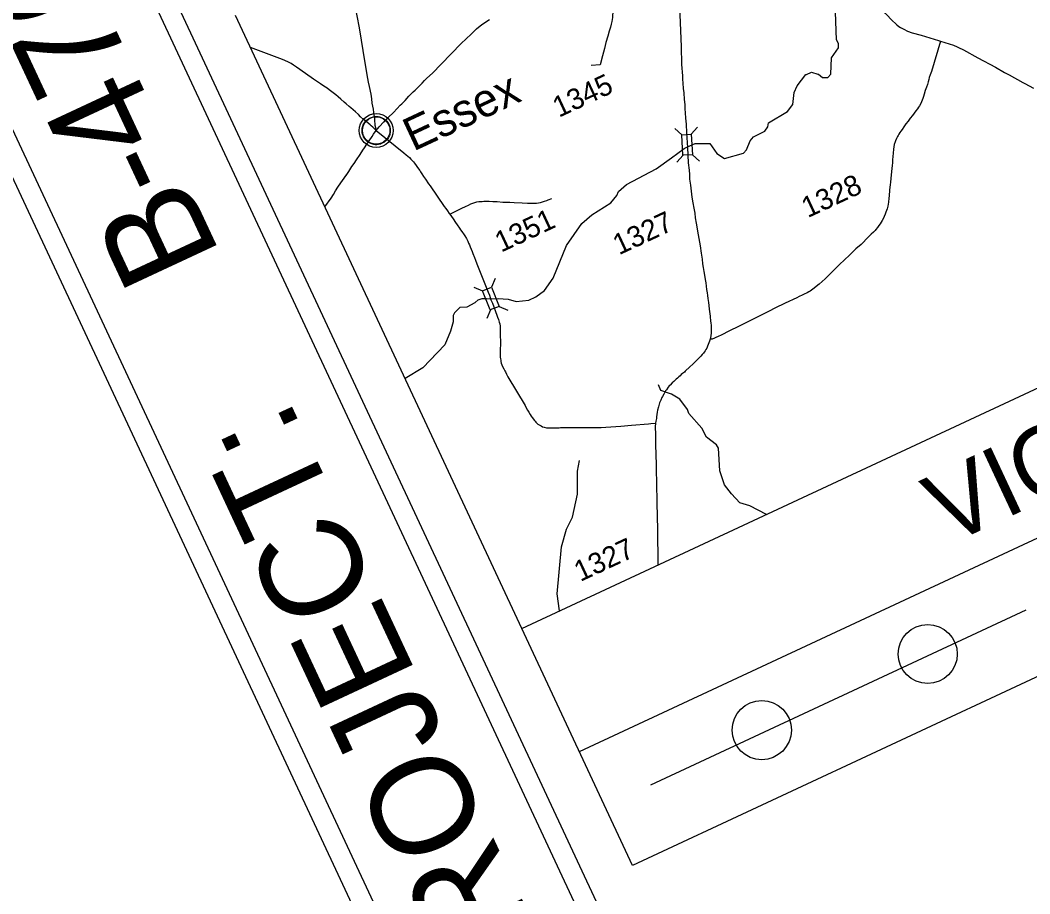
# Model space of a CAD drawing. Extents: x 2318983 to 2324558, y 920396 to 924651.
# Drawn here: x 2320105 to 2320702, y 922262 to 922780 of the extents above; entities that cross this region are included whole.
import ezdxf

# ---------------------------------------------------------------- set-up
doc = ezdxf.new("R2010")
doc.units = 0
for name, color, linetype in [('Exist Civil Demographics City Label', 7, 'Continuous'), ('Exist Civil Demographics Community CELL', 7, 'Continuous'), ('Exist Hydrographic Creek Single Shore', 7, 'Continuous'), ('Exist Road Primary NC Attributed', 7, 'Continuous'), ('Exist Road Secondary Structure Standard Bridge CELL', 7, 'Continuous'), ('Exist Road Secondary Type 51 Attributed', 7, 'Continuous'), ('Exist Road Secondary Type 51 Number Label', 7, 'Continuous'), ('Pattern 3', 7, 'Continuous'), ('Sheet Title CELL', 7, 'Continuous')]:
    doc.layers.add(name, color=color, linetype=linetype)

msp = doc.modelspace()

# ---------------------------------------------------------------- linework, layer by layer
at = {"layer": 'Exist Civil Demographics Community CELL'}
msp.add_lwpolyline([(2320307.18, 922715.51), (2320307.28, 922716.1), (2320307.47, 922716.8), (2320307.78, 922717.57), (2320308.09, 922718.18), (2320308.45, 922718.79), (2320308.85, 922719.33), (2320309.27, 922719.8), (2320309.75, 922720.29), (2320310.34, 922720.77), (2320310.92, 922721.16), (2320311.44, 922721.47), (2320311.98, 922721.73), (2320312.56, 922721.97), (2320313.15, 922722.17), (2320313.61, 922722.29), (2320314.13, 922722.37), (2320314.57, 922722.44), (2320315.25, 922722.47), (2320315.72, 922722.46), (2320316.32, 922722.43), (2320316.84, 922722.35), (2320317.36, 922722.25), (2320317.89, 922722.1), (2320318.44, 922721.89), (2320319.15, 922721.58), (2320319.82, 922721.21), (2320320.35, 922720.84), (2320320.9, 922720.41), (2320321.25, 922720.08), (2320321.69, 922719.61), (2320322.1, 922719.11), (2320322.43, 922718.62), (2320322.76, 922718.09), (2320323.02, 922717.54), (2320323.24, 922717.01), (2320323.41, 922716.48), (2320323.54, 922715.99), (2320323.66, 922715.34), (2320323.72, 922714.85), (2320323.75, 922714.21), (2320323.73, 922713.59), (2320323.67, 922712.99), (2320323.57, 922712.41), (2320323.4, 922711.75), (2320323.2, 922711.13), (2320322.95, 922710.59), (2320322.62, 922709.95), (2320322.27, 922709.39), (2320321.9, 922708.89), (2320321.45, 922708.38), (2320320.89, 922707.86), (2320320.36, 922707.42), (2320319.83, 922707.05), (2320319.37, 922706.79), (2320318.64, 922706.44), (2320317.88, 922706.15), (2320317.25, 922706), (2320316.55, 922705.86), (2320316.08, 922705.81), (2320315.6, 922705.78), (2320315.01, 922705.78), (2320314.55, 922705.83), (2320313.95, 922705.91), (2320313.32, 922706.04), (2320312.84, 922706.18), (2320312.29, 922706.38), (2320311.8, 922706.59), (2320311.38, 922706.83), (2320310.66, 922707.26), (2320310.07, 922707.72), (2320309.54, 922708.2), (2320309.07, 922708.71), (2320308.73, 922709.13), (2320308.42, 922709.58), (2320307.98, 922710.33), (2320307.8, 922710.71), (2320307.61, 922711.14), (2320307.34, 922712.01), (2320307.18, 922712.75), (2320307.1, 922713.3), (2320307.07, 922713.97), (2320307.06, 922714.47), (2320307.12, 922715.16)], close=True, dxfattribs=at)
for centre, radius in [((2320315.43, 922714.19), 10.03), ((2320315.4, 922714.22), 8.15)]:
    msp.add_circle(centre, radius, dxfattribs=at)
at = {"layer": 'Exist Hydrographic Creek Single Shore'}
for points in [[(2320569.9, 922747.45), (2320570.2, 922747.45), (2320573.22, 922748.68), (2320576.86, 922747.53), (2320577.28, 922747.53), (2320579.77, 922745.64), (2320582.84, 922745.68), (2320584.66, 922747.61), (2320585.03, 922757.16), (2320589.07, 922763.14), (2320589.24, 922765.65), (2320587.98, 922767.86), (2320587.39, 922784.23)], [(2320458.96, 922678.09), (2320463.64, 922682.08), (2320481.15, 922691.44), (2320490.31, 922697.95), (2320497.86, 922703.42), (2320499.84, 922704.47), (2320504.27, 922706.5), (2320513.06, 922706.43), (2320517.02, 922700.5), (2320521.68, 922697.62), (2320532.9, 922700.83), (2320534.72, 922702.68), (2320536.93, 922708.02), (2320538.75, 922710.36), (2320545.47, 922713.86), (2320547.29, 922716.36), (2320547.68, 922718.64), (2320558.88, 922725.48), (2320562.1, 922729.65), (2320562.86, 922736.79), (2320564.66, 922740.74), (2320569.9, 922747.45)], [(2320365.22, 922609.48), (2320369.31, 922609.73), (2320374, 922612.18), (2320375.85, 922613.75), (2320378.12, 922614.68), (2320380.69, 922614.52), (2320383.29, 922614.46), (2320387.65, 922614.62), (2320393.49, 922614.14), (2320398.38, 922612.86), (2320405.74, 922613.56), (2320410.02, 922615.52), (2320415.11, 922619.44), (2320420.16, 922626.67), (2320428.16, 922645.98), (2320437.24, 922659.03), (2320443.11, 922664.2), (2320454.31, 922671.28), (2320457.95, 922675.63), (2320458.96, 922678.09)], [(2320365.22, 922609.48), (2320361.77, 922606.11), (2320360.96, 922604.46), (2320361.01, 922600.83), (2320359.41, 922595.27), (2320356.02, 922587.22), (2320343.05, 922573.52), (2320332.54, 922567.22)], [(2320365.22, 922609.48), (2320361.77, 922606.11), (2320360.96, 922604.46), (2320361.01, 922600.83), (2320359.41, 922595.27), (2320356.02, 922587.22), (2320347.23, 922577.93)], [(2320546.51, 922486.67), (2320536.59, 922491.83), (2320530.83, 922493.61), (2320525.86, 922498.9), (2320521.7, 922504.14), (2320518.95, 922512.5), (2320518.18, 922525.88), (2320516.95, 922527.85), (2320510.95, 922532.36), (2320508.22, 922537.82), (2320500.54, 922546.55), (2320499.7, 922548.78), (2320495.13, 922554.89), (2320490.18, 922557.92), (2320484.01, 922560.09), (2320482.53, 922563.42)], [(2320423.87, 922429.44), (2320422.57, 922439.58), (2320425.15, 922467.47), (2320428.11, 922477.93), (2320431.72, 922484.94), (2320434.65, 922498.71), (2320434.7, 922512.27), (2320435.88, 922518.62)]]:
    msp.add_lwpolyline(points, dxfattribs=at)
at = {"layer": 'Exist Road Primary NC Attributed'}
for points in [[(2320315.43, 922714.19), (2320315.17, 922715.67), (2320314.86, 922717.21), (2320314.84, 922717.95), (2320314.66, 922719.97), (2320314.55, 922721.75), (2320314.28, 922723.39), (2320314.06, 922724.88), (2320313.72, 922726.83), (2320313.08, 922730.29), (2320312.74, 922732.88), (2320312.34, 922735.7), (2320311.42, 922740.16), (2320310.86, 922742.81), (2320310.51, 922744.91), (2320308.84, 922754.21), (2320305.49, 922774.93), (2320299.94, 922803.69)], [(2320315.43, 922714.19), (2320317.24, 922716.31), (2320319.96, 922719.27), (2320321.06, 922720.21), (2320322.53, 922721.81), (2320325.55, 922724.79), (2320327.74, 922727.12), (2320329.64, 922729.11), (2320330.52, 922730.06), (2320332.54, 922732.03), (2320334.82, 922734.62), (2320337.27, 922737.02), (2320338.48, 922738.15), (2320339.22, 922738.9), (2320340.57, 922740.27), (2320342.57, 922742.22), (2320344.05, 922743.83), (2320345.43, 922745.21), (2320348.71, 922748.23), (2320353.79, 922753.46), (2320365.72, 922765.79), (2320371.58, 922771.35), (2320374.89, 922774.33), (2320377.97, 922776.95), (2320382.43, 922780.03)], [(2320285.03, 922669.02), (2320288.7, 922674.16), (2320290.05, 922676.19), (2320291.39, 922678.38), (2320292.78, 922680.5), (2320294.5, 922683.07), (2320296.5, 922685.95), (2320297.96, 922688.18), (2320299.12, 922689.95), (2320301.02, 922692.86), (2320302.27, 922694.68), (2320303.7, 922696.73), (2320305.85, 922699.87), (2320307.48, 922702.43), (2320308.48, 922703.87), (2320309.76, 922706.01), (2320311.21, 922707.97), (2320313.03, 922710.67), (2320313.86, 922711.94), (2320315.43, 922714.19)], [(2320296.68, 922686.23), (2320297.96, 922688.18), (2320299.12, 922689.95), (2320301.02, 922692.86), (2320302.27, 922694.68), (2320303.7, 922696.73), (2320305.85, 922699.87), (2320307.48, 922702.43), (2320308.48, 922703.87), (2320309.76, 922706.01), (2320311.21, 922707.97), (2320313.03, 922710.67), (2320313.86, 922711.94), (2320315.43, 922714.19)]]:
    msp.add_lwpolyline(points, dxfattribs=at)
at = {"layer": 'Exist Road Secondary Structure Standard Bridge CELL'}
for p, q in [((2320492.16, 922715.36), (2320496.31, 922711.66)), ((2320505.71, 922716.14), (2320502, 922711.98)), ((2320497.11, 922699.48), (2320493.4, 922695.33)), ((2320502.67, 922699.8), (2320506.82, 922696.09)), ((2320385.84, 922626.4), (2320383.67, 922621.27)), ((2320373.26, 922621.3), (2320378.39, 922619.13)), ((2320383.07, 922607.86), (2320380.9, 922602.73)), ((2320388.23, 922609.95), (2320393.36, 922607.78))]:
    msp.add_line(p, q, dxfattribs=at)
for points in [[(2320502, 922711.98), (2320502.69, 922699.8), (2320497.01, 922699.48), (2320496.31, 922711.66)], [(2320383.67, 922621.27), (2320388.25, 922609.96), (2320382.97, 922607.82), (2320378.39, 922619.13)]]:
    msp.add_lwpolyline(points, close=True, dxfattribs=at)
at = {"layer": 'Exist Road Secondary Type 51 Attributed'}
for points in [[(2320456.12, 922794.03), (2320456.36, 922791.13), (2320456.12, 922788.51), (2320455.49, 922785.39), (2320455.28, 922781.06), (2320454.97, 922778.68), (2320454.55, 922777.29), (2320454.06, 922775.37), (2320453.4, 922772.96), (2320452.56, 922769.99), (2320451.48, 922766.32), (2320450.5, 922762.69), (2320449.39, 922758.33), (2320448.11, 922753.14), (2320442.71, 922752.73)], [(2320606.71, 922790.64), (2320608.32, 922789.8), (2320610.8, 922788.47), (2320613.42, 922786.73), (2320617.89, 922782.46), (2320620.39, 922779.88), (2320623.65, 922776.77), (2320624.82, 922775.89), (2320625.95, 922775.2), (2320627.88, 922774.15), (2320630.06, 922773.1), (2320632.8, 922772.14), (2320638.08, 922770.6), (2320648.35, 922767.6), (2320649.52, 922767.2)], [(2320494.97, 922787.68), (2320494.98, 922787.49), (2320495.9, 922763.88), (2320496.28, 922753.33), (2320496.74, 922746.52), (2320496.86, 922744.52), (2320497.03, 922742.29), (2320497.27, 922739.14), (2320497.55, 922736.47), (2320497.86, 922732.63), (2320498.1, 922729.68), (2320498.23, 922727.01), (2320498.37, 922724.61), (2320498.58, 922721.49), (2320498.88, 922717.9), (2320499.23, 922712.89), (2320499.68, 922704.04)], [(2320649.52, 922767.2), (2320644.16, 922749.08), (2320643.46, 922747.11), (2320642.93, 922745.51), (2320642.67, 922744.37), (2320642.33, 922743.09), (2320641.77, 922741.51), (2320641.24, 922739.77), (2320640.54, 922737.8), (2320639.91, 922735.76), (2320639.52, 922734.36), (2320639.12, 922733.23), (2320638.73, 922732.16), (2320638.36, 922731.25), (2320637.82, 922730.26), (2320637.13, 922728.77), (2320636.62, 922728.1), (2320635.9, 922726.94), (2320634.99, 922725.77), (2320633.95, 922724.38), (2320632.98, 922723.13), (2320631.61, 922721.39), (2320630.35, 922719.74), (2320629.1, 922718.18), (2320627.85, 922716.4), (2320626.83, 922714.79), (2320626.04, 922713.77), (2320625.48, 922712.94), (2320624.97, 922712.05), (2320624.48, 922711.29), (2320624.09, 922710.57), (2320623.76, 922709.87), (2320623.53, 922709.45), (2320622.98, 922708.09), (2320622.65, 922707.43), (2320622.17, 922705.96), (2320621.66, 922703.02), (2320621.44, 922700.81), (2320621.32, 922698.76), (2320621.15, 922696.72), (2320621.06, 922695.31), (2320620.85, 922693.18), (2320620.72, 922691.86), (2320620.21, 922685.77), (2320619.87, 922683.6), (2320619.7, 922682.02), (2320619.61, 922680.66), (2320619.44, 922678.74), (2320619.13, 922675.45), (2320618.95, 922674.16), (2320618.8, 922671.76), (2320618.38, 922669.4), (2320617.95, 922667.71), (2320617.57, 922666.68), (2320617.27, 922665.79), (2320616.85, 922664.64), (2320616.21, 922663.28), (2320615.78, 922662.13), (2320615.1, 922660.89), (2320613.78, 922658.93), (2320613.14, 922657.91), (2320612.2, 922656.63), (2320611.18, 922655.48), (2320610.8, 922654.93), (2320609.91, 922653.95), (2320608.5, 922652.71), (2320606.88, 922651.18), (2320602.54, 922646.7), (2320599.52, 922644.01), (2320596.35, 922640.88), (2320592.16, 922636.99), (2320590.4, 922635.33), (2320586.74, 922631.84), (2320583.55, 922628.59), (2320581.22, 922626.2), (2320577.66, 922623.02), (2320574, 922620.08), (2320573.12, 922619.52), (2320572.29, 922618.97), (2320571.66, 922618.62), (2320570.68, 922618.07), (2320568.77, 922617.16), (2320567.55, 922616.51), (2320565.84, 922615.71), (2320564.51, 922615.1), (2320557.51, 922611.88), (2320551.54, 922608.81), (2320548.07, 922607.1), (2320529.58, 922597.9), (2320525, 922595.62), (2320519.2, 922592.71), (2320518.31, 922592.34), (2320516.05, 922591.28), (2320515.3, 922590.88), (2320514.7, 922590.63), (2320514.31, 922590.52), (2320513.91, 922590.45), (2320513.2, 922590.42)], [(2320649.52, 922767.2), (2320657.3, 922764.7), (2320659.35, 922763.77), (2320660.2, 922763.4), (2320663.14, 922762.04), (2320671.6, 922757.31), (2320682.09, 922751.67), (2320687.38, 922748.62), (2320688.64, 922748.02), (2320690.3, 922747.13), (2320698.36, 922742.71), (2320699.45, 922742.03), (2320702.02, 922740.69), (2320704.64, 922739.24)], [(2320315.43, 922714.19), (2320313.33, 922716.16), (2320312.46, 922716.95), (2320311.84, 922717.52), (2320310.62, 922718.53), (2320309.47, 922719.45), (2320307.93, 922720.76), (2320306.1, 922722.36), (2320304.86, 922723.58), (2320303.07, 922725.23), (2320301.68, 922726.5), (2320300.44, 922727.52), (2320299.34, 922728.49), (2320297.66, 922729.9), (2320296.41, 922731.02), (2320294.43, 922732.72), (2320292.84, 922734.08), (2320291.55, 922735.24), (2320289.12, 922737.09), (2320287.58, 922738.3), (2320286.29, 922739.27), (2320284.46, 922740.53), (2320282.49, 922741.87), (2320278.23, 922744.69), (2320270.18, 922750.24), (2320268.19, 922751.64), (2320266.48, 922752.86), (2320265.05, 922753.84), (2320263.06, 922754.96), (2320259.99, 922756.25), (2320250.52, 922759.79), (2320240.95, 922763.46)], [(2320315.43, 922714.19), (2320313.33, 922716.16), (2320312.46, 922716.95), (2320311.84, 922717.52), (2320310.62, 922718.53), (2320309.47, 922719.45), (2320307.93, 922720.76), (2320306.1, 922722.36), (2320304.86, 922723.58), (2320303.07, 922725.23), (2320301.68, 922726.5), (2320300.44, 922727.52), (2320299.34, 922728.49), (2320297.66, 922729.9), (2320296.41, 922731.02), (2320294.43, 922732.72), (2320292.84, 922734.08), (2320291.55, 922735.24), (2320289.12, 922737.09), (2320287.58, 922738.3), (2320286.29, 922739.27), (2320284.46, 922740.53), (2320282.49, 922741.87), (2320278.23, 922744.69), (2320270.18, 922750.24), (2320268.19, 922751.64), (2320266.48, 922752.86), (2320265.17, 922753.76)], [(2320315.43, 922714.19), (2320331.71, 922701.03), (2320333.2, 922699.82), (2320334.23, 922698.9), (2320335.13, 922698.1), (2320335.95, 922697.25), (2320336.75, 922696.43), (2320337.42, 922695.63), (2320338.06, 922694.78), (2320339.16, 922693.34), (2320339.94, 922692.29), (2320341.17, 922690.49), (2320341.68, 922689.64), (2320342.42, 922688.42), (2320343.42, 922686.95), (2320344.57, 922685.34), (2320346.42, 922682.66), (2320347.29, 922681.48), (2320355.67, 922669.21), (2320356.7, 922667.9), (2320357.6, 922666.51), (2320358.71, 922665.04), (2320359, 922664.6)], [(2320499.68, 922704.04), (2320499.91, 922699.53), (2320500.22, 922694.97), (2320500.66, 922690.75), (2320500.84, 922688.18), (2320500.97, 922685.31), (2320501.45, 922681.74), (2320501.9, 922678.28), (2320502.38, 922674.58), (2320502.96, 922671.32), (2320503.51, 922668.07), (2320503.99, 922665.16), (2320504.33, 922662.45), (2320504.88, 922659.26), (2320506.01, 922652.37), (2320507.16, 922645.91), (2320507.76, 922641.53), (2320508.34, 922637.88), (2320508.71, 922635.24), (2320509.06, 922632.94), (2320509.5, 922630.61), (2320509.81, 922628.42), (2320510.22, 922625.78), (2320510.53, 922623.83), (2320510.84, 922621.94), (2320511.08, 922619.92), (2320511.38, 922618.07), (2320511.59, 922616.36), (2320511.8, 922614.64), (2320512.16, 922612.33), (2320512.42, 922610.56), (2320512.64, 922608.35), (2320512.8, 922606.83), (2320513.17, 922604.06), (2320513.24, 922603.49), (2320513.41, 922601.66), (2320513.58, 922599.84), (2320513.68, 922599.02), (2320513.78, 922598.02), (2320513.82, 922596.89), (2320513.81, 922596.01), (2320513.77, 922595.18), (2320513.78, 922594.26), (2320513.58, 922592.47), (2320513.2, 922590.42)], [(2320359, 922664.6), (2320361.47, 922665.79), (2320364.09, 922667.11), (2320366.21, 922668.19), (2320368.3, 922669.15), (2320370.03, 922670), (2320371.5, 922670.66), (2320372.66, 922671.08), (2320373.81, 922671.47), (2320375.05, 922671.81), (2320376.13, 922672.01), (2320377.17, 922672.08), (2320378.17, 922672.16), (2320379.21, 922672.24), (2320382.3, 922672.24), (2320384.42, 922672.12), (2320387.04, 922672.01), (2320390.4, 922671.78), (2320391.79, 922671.74), (2320393.06, 922671.66), (2320394.45, 922671.66), (2320397.07, 922671.54), (2320401.89, 922671.31), (2320404.9, 922671.12), (2320407.48, 922671.04), (2320409.3, 922671.04), (2320410.38, 922671.12), (2320411.42, 922671.27), (2320412.65, 922671.47), (2320413.85, 922671.89), (2320415.12, 922672.28), (2320416.36, 922672.78), (2320417.32, 922673.13), (2320419.36, 922673.82)], [(2320359, 922664.6), (2320359.93, 922663.25), (2320360.89, 922661.78), (2320362.42, 922659.59), (2320363.34, 922658.22), (2320364.74, 922656.2), (2320365.42, 922655.3), (2320366.1, 922654.35), (2320366.49, 922653.71), (2320367.07, 922652.93), (2320367.87, 922651.8), (2320368.82, 922650.21), (2320369.6, 922648.66), (2320370.12, 922647.48), (2320370.57, 922646.35), (2320371.13, 922645.15), (2320372.19, 922642.45), (2320372.59, 922641.37), (2320373.55, 922638.88), (2320374.11, 922637.41), (2320375.04, 922635.11), (2320381.72, 922618.37), (2320382.44, 922616.51), (2320383.23, 922613.89)], [(2320383.23, 922613.89), (2320384.2, 922611.81), (2320385.09, 922609.61), (2320386.07, 922606.96), (2320386.82, 922604.77), (2320387.29, 922603.58), (2320387.79, 922602.25), (2320388.09, 922601.41), (2320388.31, 922600.61), (2320388.58, 922599.66), (2320388.74, 922598.19), (2320388.76, 922596.98), (2320388.91, 922592.07), (2320388.93, 922589.8), (2320388.97, 922586.75), (2320388.83, 922585.23), (2320388.85, 922583.95), (2320388.82, 922582.52), (2320388.83, 922581), (2320388.9, 922579.82), (2320389, 922578.83), (2320389.11, 922578), (2320389.28, 922577.18), (2320389.47, 922576.38), (2320389.73, 922575.35), (2320390.23, 922574.22), (2320390.89, 922572.9), (2320391.49, 922571.83), (2320391.89, 922571.09), (2320392.59, 922569.73), (2320393.45, 922568.21), (2320403.56, 922551.15), (2320404.22, 922549.83), (2320405.07, 922548.51), (2320405.82, 922547.24), (2320406.58, 922545.87), (2320407.18, 922544.84), (2320407.77, 922544.06), (2320408.54, 922543.17), (2320408.97, 922542.49), (2320409.48, 922541.84), (2320409.87, 922541.39), (2320410.47, 922540.7), (2320411.21, 922540.07), (2320411.84, 922539.71), (2320412.6, 922539.3), (2320413.12, 922539.06), (2320413.97, 922538.62), (2320414.84, 922538.35), (2320416.2, 922538.05), (2320417.48, 922537.92), (2320418.81, 922537.88), (2320421.07, 922537.91), (2320422.15, 922537.97), (2320423.78, 922538.04), (2320424.61, 922538.1), (2320441.24, 922538.13), (2320443.06, 922538.14), (2320444.24, 922538.11), (2320448.71, 922538.16), (2320451.42, 922538.38), (2320460.36, 922538.87), (2320466.65, 922539.53), (2320476.58, 922540.37), (2320478.06, 922540.44), (2320480.81, 922540.67)], [(2320513.2, 922590.42), (2320512.7, 922589.36), (2320512.36, 922588.42), (2320512.03, 922587.34), (2320511.6, 922586.35), (2320511.12, 922585.26), (2320510.68, 922584.47), (2320510.16, 922583.58), (2320509.62, 922582.74), (2320509.12, 922582.23), (2320508.48, 922581.51), (2320507.55, 922580.51), (2320507.27, 922580.13), (2320506.45, 922579.31), (2320505.63, 922578.44), (2320504.64, 922577.54), (2320503.61, 922576.52), (2320502.87, 922575.77), (2320501.08, 922574.21), (2320498.44, 922571.57), (2320497.9, 922571.05), (2320496.87, 922570.21), (2320496.09, 922569.55), (2320495.31, 922568.86), (2320494.53, 922568.21), (2320493.75, 922567.42), (2320493.02, 922566.72), (2320492.32, 922566.06), (2320491.67, 922565.48), (2320490.63, 922564.6), (2320489.44, 922563.33), (2320488.96, 922562.78), (2320488.36, 922562.1), (2320487.33, 922560.56), (2320486.75, 922559.81), (2320485.68, 922557.98), (2320484.86, 922556.5), (2320484.63, 922555.91), (2320483.86, 922554.37), (2320483.47, 922553.53), (2320483.24, 922552.79), (2320482.9, 922551.95), (2320482.71, 922551.12), (2320482.48, 922550.32), (2320482.05, 922548.5), (2320481.87, 922547.31), (2320481.45, 922544.51), (2320481.32, 922543.52), (2320480.99, 922541.9), (2320480.81, 922540.67)], [(2320480.81, 922540.67), (2320480.62, 922538.58), (2320480.76, 922534), (2320480.85, 922529.56), (2320480.89, 922526.43), (2320480.98, 922523.48), (2320481.08, 922521.53), (2320481.12, 922516.73), (2320481.26, 922512.06), (2320481.39, 922506.07), (2320481.48, 922500.67), (2320481.57, 922498.18), (2320481.57, 922495.28), (2320481.57, 922491.15), (2320481.76, 922487.84), (2320481.8, 922483.71), (2320481.94, 922479.5), (2320481.98, 922470.74), (2320482.12, 922464.35), (2320482.18, 922456.65)]]:
    msp.add_lwpolyline(points, dxfattribs=at)
at = {"layer": 'Pattern 3'}
for p, q in [((2320401.68, 922419.08), (2320232.17, 922782.28)), ((2320435.73, 922346.11), (2321310.81, 922754.51)), ((2320478.11, 922326.42), (2320700.24, 922430.09))]:
    msp.add_line(p, q, dxfattribs=at)
msp.add_lwpolyline([(2320401.68, 922419.08), (2321276.76, 922827.48), (2321342.28, 922687.08), (2320467.2, 922278.68)], close=True, dxfattribs=at)
for centre in [(2320641.98, 922403.92), (2320543.72, 922358.81)]:
    msp.add_circle(centre, 17.51, dxfattribs=at)
at = {"layer": 'Sheet Title CELL'}
for p, q in [((2320909.23, 921264.35), (2320061.71, 923080.32)), ((2321086.13, 920856.94), (2320050.84, 923075.24))]:
    msp.add_line(p, q, dxfattribs=at)
for points in [[(2319937.02, 923035.37), (2320982.47, 920795.32)], [(2319937.02, 923035.37), (2320982.47, 920795.32)], [(2319953, 923029.58), (2320988.27, 920811.27)]]:
    msp.add_lwpolyline(points, dxfattribs=at)

# ---------------------------------------------------------------- texts
at = {"layer": 'Exist Civil Demographics City Label'}
msp.add_text('Essex', height=19.683, rotation=25.01869, dxfattribs=at).set_placement((2320337.37, 922701.61))
at = {"layer": 'Exist Road Secondary Type 51 Number Label'}
for s, p in [('1345', (2320423.56, 922721.65)), ('1328', (2320570.94, 922662.18)), ('1351', (2320389.35, 922641.72)), ('1327', (2320459.19, 922640.17)), ('1327', (2320436.24, 922446.57))]:
    msp.add_text(s, height=12.302, rotation=25.01869, dxfattribs=at).set_placement(p)
at = {"layer": 'Pattern 3'}
msp.add_text('VICINITY MAP', height=42, rotation=25.01875, dxfattribs=at).set_placement((2320653.81, 922468.05))
at = {"layer": 'Sheet Title CELL'}
for s, height, p in [(' B-4761  ', 60, (2320233.08, 922620.13)), ('TIP PROJECT:', 59.9999, (2320492.48, 922064.33))]:
    msp.add_text(s, height=height, rotation=115.01869, dxfattribs=at).set_placement(p)

doc.saveas('drawing.dxf')
